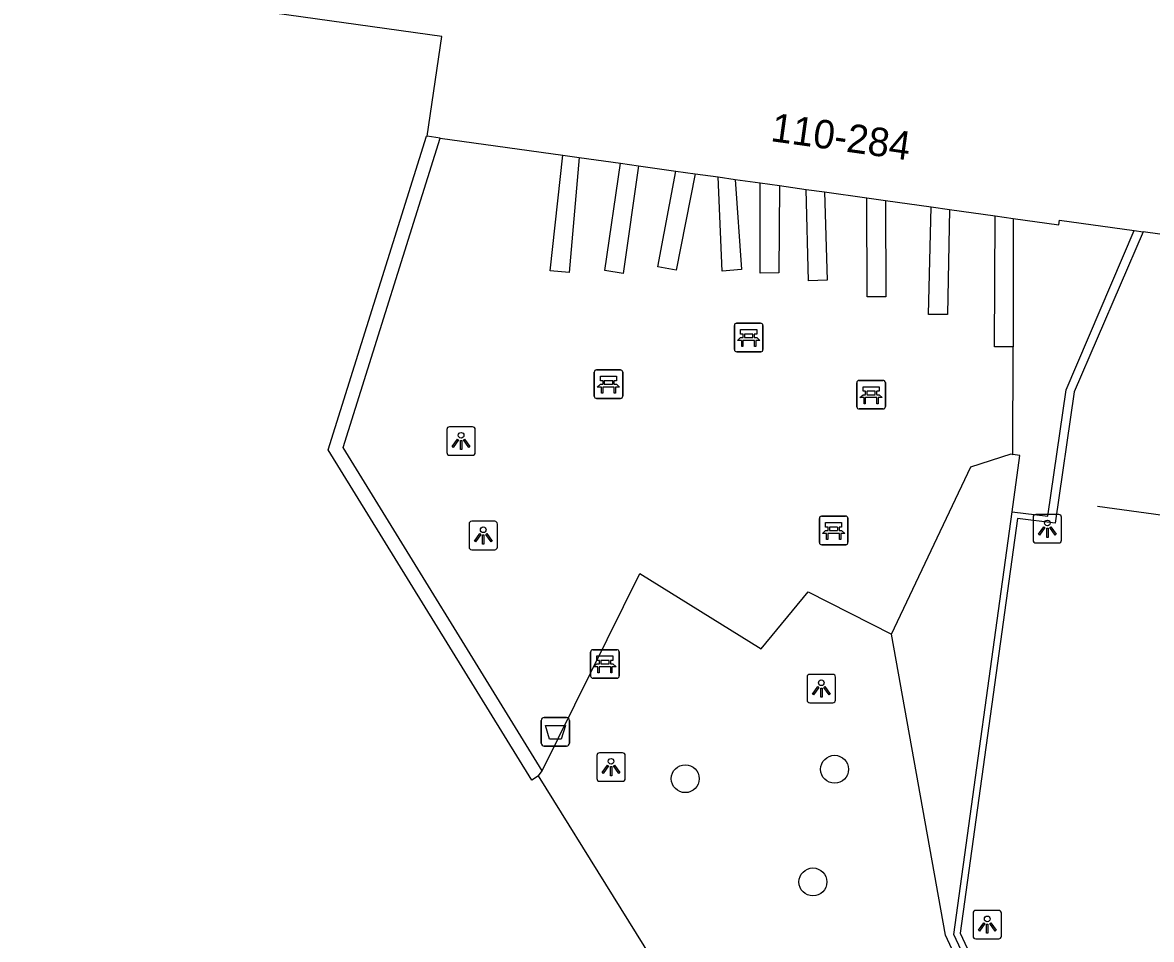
# Model space of a CAD drawing. Extents: x 155640 to 156810, y 382822 to 384046.
# Drawn here: x 156370.31 to 156409.89, y 383660.45 to 383692.57 of the extents above; entities that cross this region are included whole.
import ezdxf

# ---------------------------------------------------------------- set-up
doc = ezdxf.new("R2010")
doc.units = 0
for name, color, linetype in [('IMGEO_Afvalbak', 7, 'Continuous'), ('IMGEO_Bank', 7, 'Continuous'), ('IMGEO_Boom', 7, 'Continuous'), ('IMGEO_Lichtpunt', 7, 'Continuous'), ('IMGEO_Lijnafwatering', 7, 'Continuous'), ('IMGEO_Meer_plas_ven_vijver', 7, 'Continuous'), ('IMGEO_Muur', 7, 'Continuous'), ('IMGEO_Pand', 7, 'Continuous'), ('IMGEO_Pand_nummerreeks', 7, 'Continuous'), ('IMGEO_Voetpad_open', 7, 'Continuous')]:
    doc.layers.add(name, color=color, linetype=linetype)

msp = doc.modelspace()

# ---------------------------------------------------------------- linework, layer by layer
at = {"layer": 'IMGEO_Afvalbak'}
for p, q in [((156388.497, 383667.324), (156388.497, 383668.124)), ((156388.497, 383668.124), (156388.497, 383667.324)), ((156388.597, 383668.224), (156389.387, 383668.224)), ((156389.387, 383668.224), (156388.597, 383668.224)), ((156389.487, 383668.124), (156389.487, 383667.324)), ((156389.487, 383667.324), (156389.487, 383668.124)), ((156389.387, 383667.224), (156388.597, 383667.224)), ((156388.597, 383667.224), (156389.387, 383667.224))]:
    msp.add_line(p, q, dxfattribs=at)
msp.add_lwpolyline([(156388.64, 383667.938), (156389.344, 383667.938), (156389.195, 383667.468), (156388.789, 383667.468), (156388.64, 383667.938)], dxfattribs=at)
for centre, start, end in [((156388.597, 383668.124), 90, 180), ((156388.597, 383668.124), 90, 180), ((156389.387, 383668.124), 0, 90), ((156389.387, 383668.124), 360, 90), ((156388.597, 383667.324), 180, 270), ((156388.597, 383667.324), 180, 270), ((156389.387, 383667.324), 270, 0), ((156389.387, 383667.324), 270, 0)]:
    msp.add_arc(centre, 0.1, start, end, dxfattribs=at)
at = {"layer": 'IMGEO_Bank'}
for p, q in [((156395.27, 383681.114), (156395.27, 383681.955)), ((156395.27, 383681.955), (156395.27, 383681.114)), ((156395.345, 383682.039), (156396.186, 383682.039)), ((156396.186, 383682.039), (156395.345, 383682.039)), ((156396.27, 383681.964), (156396.27, 383681.123)), ((156396.27, 383681.123), (156396.27, 383681.964)), ((156395.967, 383681.437), (156395.574, 383681.437)), ((156395.579, 383681.545), (156395.579, 383681.651)), ((156395.623, 383681.651), (156395.623, 383681.545)), ((156395.911, 383681.657), (156395.629, 383681.657)), ((156395.629, 383681.539), (156395.911, 383681.539)), ((156395.917, 383681.545), (156395.917, 383681.651)), ((156395.961, 383681.651), (156395.961, 383681.545)), ((156396.195, 383681.039), (156395.354, 383681.039)), ((156395.354, 383681.039), (156396.195, 383681.039)), ((156390.354, 383679.479), (156390.354, 383680.32)), ((156390.354, 383680.32), (156390.354, 383679.479)), ((156390.429, 383680.404), (156391.27, 383680.404)), ((156391.27, 383680.404), (156390.429, 383680.404)), ((156391.354, 383680.329), (156391.354, 383679.488)), ((156391.354, 383679.488), (156391.354, 383680.329)), ((156391.051, 383679.802), (156390.658, 383679.802)), ((156390.663, 383679.91), (156390.663, 383680.016)), ((156390.707, 383680.016), (156390.707, 383679.91)), ((156390.995, 383680.022), (156390.713, 383680.022)), ((156390.713, 383679.904), (156390.995, 383679.904)), ((156391.001, 383679.91), (156391.001, 383680.016)), ((156391.045, 383680.016), (156391.045, 383679.91)), ((156399.562, 383679.111), (156399.562, 383679.952)), ((156399.562, 383679.952), (156399.562, 383679.111)), ((156399.637, 383680.036), (156400.478, 383680.036)), ((156400.478, 383680.036), (156399.637, 383680.036)), ((156400.562, 383679.961), (156400.562, 383679.12)), ((156400.562, 383679.12), (156400.562, 383679.961)), ((156391.279, 383679.404), (156390.438, 383679.404)), ((156390.438, 383679.404), (156391.279, 383679.404)), ((156400.259, 383679.434), (156399.866, 383679.434)), ((156399.871, 383679.542), (156399.871, 383679.648)), ((156399.915, 383679.648), (156399.915, 383679.542)), ((156400.203, 383679.654), (156399.921, 383679.654)), ((156399.921, 383679.536), (156400.203, 383679.536)), ((156400.209, 383679.542), (156400.209, 383679.648)), ((156400.253, 383679.648), (156400.253, 383679.542)), ((156400.487, 383679.036), (156399.646, 383679.036)), ((156399.646, 383679.036), (156400.487, 383679.036)), ((156398.249, 383674.354), (156398.249, 383675.195)), ((156398.249, 383675.195), (156398.249, 383674.354)), ((156398.324, 383675.279), (156399.165, 383675.279)), ((156399.165, 383675.279), (156398.324, 383675.279)), ((156399.249, 383675.204), (156399.249, 383674.363)), ((156399.249, 383674.363), (156399.249, 383675.204)), ((156398.946, 383674.677), (156398.553, 383674.677)), ((156398.558, 383674.785), (156398.558, 383674.891)), ((156398.602, 383674.891), (156398.602, 383674.785)), ((156398.89, 383674.897), (156398.608, 383674.897)), ((156398.608, 383674.779), (156398.89, 383674.779)), ((156398.896, 383674.785), (156398.896, 383674.891)), ((156398.94, 383674.891), (156398.94, 383674.785)), ((156399.174, 383674.279), (156398.333, 383674.279)), ((156398.333, 383674.279), (156399.174, 383674.279)), ((156390.228, 383669.675), (156390.228, 383670.516)), ((156390.228, 383670.516), (156390.228, 383669.675)), ((156390.303, 383670.6), (156391.144, 383670.6)), ((156391.144, 383670.6), (156390.303, 383670.6)), ((156390.537, 383670.106), (156390.537, 383670.212)), ((156390.581, 383670.212), (156390.581, 383670.106)), ((156390.869, 383670.218), (156390.587, 383670.218)), ((156390.875, 383670.106), (156390.875, 383670.212)), ((156390.919, 383670.212), (156390.919, 383670.106)), ((156391.228, 383670.525), (156391.228, 383669.684)), ((156391.228, 383669.684), (156391.228, 383670.525)), ((156390.925, 383669.998), (156390.532, 383669.998)), ((156390.587, 383670.1), (156390.869, 383670.1)), ((156391.153, 383669.6), (156390.312, 383669.6)), ((156390.312, 383669.6), (156391.153, 383669.6))]:
    msp.add_line(p, q, dxfattribs=at)
for points in [[(156395.573, 383681.657), (156395.487, 383681.657), (156395.487, 383681.818), (156396.05, 383681.818), (156396.05, 383681.657), (156395.967, 383681.657)], [(156395.517, 383681.437), (156395.375, 383681.437), (156395.487, 383681.539), (156395.573, 383681.539)], [(156395.567, 383681.43), (156395.567, 383681.223), (156395.524, 383681.223), (156395.524, 383681.43)], [(156395.967, 383681.539), (156396.05, 383681.539), (156396.162, 383681.437), (156396.023, 383681.437)], [(156396.017, 383681.43), (156396.017, 383681.223), (156395.973, 383681.223), (156395.973, 383681.43)], [(156390.657, 383680.022), (156390.571, 383680.022), (156390.571, 383680.183), (156391.134, 383680.183), (156391.134, 383680.022), (156391.051, 383680.022)], [(156390.601, 383679.802), (156390.459, 383679.802), (156390.571, 383679.904), (156390.657, 383679.904)], [(156390.651, 383679.795), (156390.651, 383679.588), (156390.608, 383679.588), (156390.608, 383679.795)], [(156391.051, 383679.904), (156391.134, 383679.904), (156391.246, 383679.802), (156391.107, 383679.802)], [(156391.101, 383679.795), (156391.101, 383679.588), (156391.057, 383679.588), (156391.057, 383679.795)], [(156399.865, 383679.654), (156399.779, 383679.654), (156399.779, 383679.815), (156400.342, 383679.815), (156400.342, 383679.654), (156400.259, 383679.654)], [(156399.809, 383679.434), (156399.667, 383679.434), (156399.779, 383679.536), (156399.865, 383679.536)], [(156399.859, 383679.427), (156399.859, 383679.22), (156399.816, 383679.22), (156399.816, 383679.427)], [(156400.259, 383679.536), (156400.342, 383679.536), (156400.454, 383679.434), (156400.315, 383679.434)], [(156400.309, 383679.427), (156400.309, 383679.22), (156400.265, 383679.22), (156400.265, 383679.427)], [(156398.552, 383674.897), (156398.466, 383674.897), (156398.466, 383675.058), (156399.029, 383675.058), (156399.029, 383674.897), (156398.946, 383674.897)], [(156398.496, 383674.677), (156398.354, 383674.677), (156398.466, 383674.779), (156398.552, 383674.779)], [(156398.546, 383674.67), (156398.546, 383674.463), (156398.503, 383674.463), (156398.503, 383674.67)], [(156398.946, 383674.779), (156399.029, 383674.779), (156399.141, 383674.677), (156399.002, 383674.677)], [(156398.996, 383674.67), (156398.996, 383674.463), (156398.952, 383674.463), (156398.952, 383674.67)], [(156390.531, 383670.218), (156390.445, 383670.218), (156390.445, 383670.379), (156391.008, 383670.379), (156391.008, 383670.218), (156390.925, 383670.218)], [(156390.475, 383669.998), (156390.333, 383669.998), (156390.445, 383670.1), (156390.531, 383670.1)], [(156390.525, 383669.991), (156390.525, 383669.784), (156390.482, 383669.784), (156390.482, 383669.991)], [(156390.925, 383670.1), (156391.008, 383670.1), (156391.12, 383669.998), (156390.981, 383669.998)], [(156390.975, 383669.991), (156390.975, 383669.784), (156390.931, 383669.784), (156390.931, 383669.991)]]:
    msp.add_lwpolyline(points, dxfattribs=at)
for centre, radius, start, end in [((156395.348, 383681.961), 0.0779, 92.4484, 184.2845), ((156395.348, 383681.961), 0.0779, 92.4484, 184.2845), ((156396.192, 383681.961), 0.0779, 2.4484, 94.2845), ((156396.192, 383681.961), 0.0779, 2.4484, 94.2845), ((156395.517, 383681.43), 0.00671, 2.8957, 87.1043), ((156395.574, 383681.43), 0.00671, 92.8957, 177.1043), ((156395.572, 383681.65), 0.00671, 2.8957, 87.1043), ((156395.572, 383681.546), 0.00671, 272.8957, 357.1043), ((156395.629, 383681.65), 0.00671, 92.8957, 177.1043), ((156395.629, 383681.546), 0.00671, 182.8957, 267.1043), ((156395.911, 383681.65), 0.00671, 2.8957, 87.1043), ((156395.911, 383681.546), 0.00671, 272.8957, 357.1043), ((156395.968, 383681.65), 0.00671, 92.8957, 177.1043), ((156395.968, 383681.546), 0.00671, 182.8957, 267.1043), ((156395.966, 383681.43), 0.00671, 2.8957, 87.1043), ((156396.023, 383681.43), 0.00671, 92.8957, 177.1043), ((156395.348, 383681.117), 0.0779, 182.4484, 274.2845), ((156395.348, 383681.117), 0.0779, 182.4484, 274.2845), ((156396.192, 383681.117), 0.0779, 272.4484, 4.2845), ((156396.192, 383681.117), 0.0779, 272.4484, 4.2845), ((156390.432, 383680.326), 0.0779, 92.4484, 184.2845), ((156390.432, 383680.326), 0.0779, 92.4484, 184.2845), ((156391.276, 383680.326), 0.0779, 2.4484, 94.2845), ((156391.276, 383680.326), 0.0779, 2.4484, 94.2845), ((156390.601, 383679.795), 0.00671, 2.8957, 87.1043), ((156390.658, 383679.795), 0.00671, 92.8957, 177.1043), ((156390.656, 383680.015), 0.00671, 2.8957, 87.1043), ((156390.656, 383679.911), 0.00671, 272.8957, 357.1043), ((156390.713, 383680.015), 0.00671, 92.8957, 177.1043), ((156390.713, 383679.911), 0.00671, 182.8957, 267.1043), ((156390.995, 383680.015), 0.00671, 2.8957, 87.1043), ((156390.995, 383679.911), 0.00671, 272.8957, 357.1043), ((156391.052, 383680.015), 0.00671, 92.8957, 177.1043), ((156391.052, 383679.911), 0.00671, 182.8957, 267.1043), ((156391.05, 383679.795), 0.00671, 2.8957, 87.1043), ((156391.107, 383679.795), 0.00671, 92.8957, 177.1043), ((156399.64, 383679.958), 0.0779, 92.4484, 184.2845), ((156399.64, 383679.958), 0.0779, 92.4484, 184.2845), ((156400.484, 383679.958), 0.0779, 2.4484, 94.2845), ((156400.484, 383679.958), 0.0779, 2.4484, 94.2845), ((156390.432, 383679.482), 0.0779, 182.4484, 274.2845), ((156390.432, 383679.482), 0.0779, 182.4484, 274.2845), ((156391.276, 383679.482), 0.0779, 272.4484, 4.2845), ((156391.276, 383679.482), 0.0779, 272.4484, 4.2845), ((156399.809, 383679.427), 0.00671, 2.8957, 87.1043), ((156399.866, 383679.427), 0.00671, 92.8957, 177.1043), ((156399.864, 383679.647), 0.00671, 2.8957, 87.1043), ((156399.864, 383679.543), 0.00671, 272.8957, 357.1043), ((156399.921, 383679.647), 0.00671, 92.8957, 177.1043), ((156399.921, 383679.543), 0.00671, 182.8957, 267.1043), ((156400.203, 383679.647), 0.00671, 2.8957, 87.1043), ((156400.203, 383679.543), 0.00671, 272.8957, 357.1043), ((156400.26, 383679.647), 0.00671, 92.8957, 177.1043), ((156400.26, 383679.543), 0.00671, 182.8957, 267.1043), ((156400.258, 383679.427), 0.00671, 2.8957, 87.1043), ((156400.315, 383679.427), 0.00671, 92.8957, 177.1043), ((156399.64, 383679.114), 0.0779, 182.4484, 274.2845), ((156399.64, 383679.114), 0.0779, 182.4484, 274.2845), ((156400.484, 383679.114), 0.0779, 272.4484, 4.2845), ((156400.484, 383679.114), 0.0779, 272.4484, 4.2845), ((156398.327, 383675.201), 0.0779, 92.4484, 184.2845), ((156398.327, 383675.201), 0.0779, 92.4484, 184.2845), ((156399.171, 383675.201), 0.0779, 2.4484, 94.2845), ((156399.171, 383675.201), 0.0779, 2.4484, 94.2845), ((156398.496, 383674.67), 0.00671, 2.8957, 87.1043), ((156398.553, 383674.67), 0.00671, 92.8957, 177.1043), ((156398.551, 383674.89), 0.00671, 2.8957, 87.1043), ((156398.551, 383674.786), 0.00671, 272.8957, 357.1043), ((156398.608, 383674.89), 0.00671, 92.8957, 177.1043), ((156398.608, 383674.786), 0.00671, 182.8957, 267.1043), ((156398.89, 383674.89), 0.00671, 2.8957, 87.1043), ((156398.89, 383674.786), 0.00671, 272.8957, 357.1043), ((156398.947, 383674.89), 0.00671, 92.8957, 177.1043), ((156398.947, 383674.786), 0.00671, 182.8957, 267.1043), ((156398.945, 383674.67), 0.00671, 2.8957, 87.1043), ((156399.002, 383674.67), 0.00671, 92.8957, 177.1043), ((156398.327, 383674.357), 0.0779, 182.4484, 274.2845), ((156398.327, 383674.357), 0.0779, 182.4484, 274.2845), ((156399.171, 383674.357), 0.0779, 272.4484, 4.2845), ((156399.171, 383674.357), 0.0779, 272.4484, 4.2845), ((156390.306, 383670.522), 0.0779, 92.4484, 184.2845), ((156390.306, 383670.522), 0.0779, 92.4484, 184.2845), ((156390.53, 383670.211), 0.00671, 2.8957, 87.1043), ((156390.587, 383670.211), 0.00671, 92.8957, 177.1043), ((156390.869, 383670.211), 0.00671, 2.8957, 87.1043), ((156390.926, 383670.211), 0.00671, 92.8957, 177.1043), ((156391.15, 383670.522), 0.0779, 2.4484, 94.2845), ((156391.15, 383670.522), 0.0779, 2.4484, 94.2845), ((156390.475, 383669.991), 0.00671, 2.8957, 87.1043), ((156390.532, 383669.991), 0.00671, 92.8957, 177.1043), ((156390.53, 383670.107), 0.00671, 272.8957, 357.1043), ((156390.587, 383670.107), 0.00671, 182.8957, 267.1043), ((156390.869, 383670.107), 0.00671, 272.8957, 357.1043), ((156390.926, 383670.107), 0.00671, 182.8957, 267.1043), ((156390.924, 383669.991), 0.00671, 2.8957, 87.1043), ((156390.981, 383669.991), 0.00671, 92.8957, 177.1043), ((156390.306, 383669.678), 0.0779, 182.4484, 274.2845), ((156390.306, 383669.678), 0.0779, 182.4484, 274.2845), ((156391.15, 383669.678), 0.0779, 272.4484, 4.2845), ((156391.15, 383669.678), 0.0779, 272.4484, 4.2845)]:
    msp.add_arc(centre, radius, start, end, dxfattribs=at)
at = {"layer": 'IMGEO_Boom'}
for centre in [(156398.781, 383666.41), (156393.545, 383666.079), (156398.021, 383662.462)]:
    msp.add_circle(centre, 0.489, dxfattribs=at)
at = {"layer": 'IMGEO_Lichtpunt'}
for p, q in [((156385.186, 383678.315), (156385.186, 383677.508)), ((156385.186, 383678.315), (156385.186, 383677.508)), ((156386.088, 383678.41), (156385.28, 383678.41)), ((156386.088, 383678.41), (156385.28, 383678.41)), ((156386.182, 383677.508), (156386.182, 383678.315)), ((156386.182, 383677.508), (156386.182, 383678.315)), ((156385.28, 383677.414), (156386.088, 383677.414)), ((156385.28, 383677.414), (156386.088, 383677.414)), ((156385.964, 383675.003), (156385.964, 383674.196)), ((156385.964, 383675.003), (156385.964, 383674.196)), ((156386.866, 383675.098), (156386.058, 383675.098)), ((156386.866, 383675.098), (156386.058, 383675.098)), ((156386.96, 383674.196), (156386.96, 383675.003)), ((156386.96, 383674.196), (156386.96, 383675.003)), ((156405.743, 383675.242), (156405.743, 383674.435)), ((156405.743, 383675.242), (156405.743, 383674.435)), ((156406.645, 383675.337), (156405.837, 383675.337)), ((156406.645, 383675.337), (156405.837, 383675.337)), ((156406.739, 383674.435), (156406.739, 383675.242)), ((156406.739, 383674.435), (156406.739, 383675.242)), ((156405.837, 383674.341), (156406.645, 383674.341)), ((156405.837, 383674.341), (156406.645, 383674.341)), ((156386.058, 383674.102), (156386.866, 383674.102)), ((156386.058, 383674.102), (156386.866, 383674.102)), ((156397.818, 383669.641), (156397.818, 383668.834)), ((156397.818, 383669.641), (156397.818, 383668.834)), ((156398.72, 383669.736), (156397.912, 383669.736)), ((156398.72, 383669.736), (156397.912, 383669.736)), ((156398.814, 383668.834), (156398.814, 383669.641)), ((156398.814, 383668.834), (156398.814, 383669.641)), ((156397.912, 383668.74), (156398.72, 383668.74)), ((156397.912, 383668.74), (156398.72, 383668.74)), ((156390.445, 383666.891), (156390.445, 383666.084)), ((156390.445, 383666.891), (156390.445, 383666.084)), ((156391.347, 383666.986), (156390.539, 383666.986)), ((156391.347, 383666.986), (156390.539, 383666.986)), ((156391.441, 383666.084), (156391.441, 383666.891)), ((156391.441, 383666.084), (156391.441, 383666.891)), ((156390.539, 383665.99), (156391.347, 383665.99)), ((156390.539, 383665.99), (156391.347, 383665.99)), ((156403.636, 383661.368), (156403.636, 383660.561)), ((156403.636, 383661.368), (156403.636, 383660.561)), ((156404.538, 383661.463), (156403.73, 383661.463)), ((156404.538, 383661.463), (156403.73, 383661.463)), ((156404.632, 383660.561), (156404.632, 383661.368)), ((156404.632, 383660.561), (156404.632, 383661.368)), ((156403.73, 383660.467), (156404.538, 383660.467)), ((156403.73, 383660.467), (156404.538, 383660.467))]:
    msp.add_line(p, q, dxfattribs=at)
for points in [[(156385.56, 383677.979), (156385.599, 383677.951), (156385.411, 383677.689), (156385.373, 383677.716), (156385.56, 383677.979)], [(156385.662, 383677.931), (156385.709, 383677.931), (156385.709, 383677.609), (156385.662, 383677.609), (156385.662, 383677.931)], [(156385.772, 383677.951), (156385.81, 383677.978), (156385.997, 383677.716), (156385.958, 383677.688), (156385.772, 383677.951)], [(156386.338, 383674.667), (156386.377, 383674.639), (156386.189, 383674.377), (156386.151, 383674.404), (156386.338, 383674.667)], [(156386.44, 383674.619), (156386.487, 383674.619), (156386.487, 383674.297), (156386.44, 383674.297), (156386.44, 383674.619)], [(156386.55, 383674.639), (156386.588, 383674.666), (156386.775, 383674.404), (156386.736, 383674.376), (156386.55, 383674.639)], [(156406.117, 383674.906), (156406.156, 383674.878), (156405.968, 383674.616), (156405.93, 383674.643), (156406.117, 383674.906)], [(156406.219, 383674.858), (156406.266, 383674.858), (156406.266, 383674.536), (156406.219, 383674.536), (156406.219, 383674.858)], [(156406.329, 383674.878), (156406.367, 383674.905), (156406.554, 383674.643), (156406.515, 383674.615), (156406.329, 383674.878)], [(156398.192, 383669.305), (156398.231, 383669.277), (156398.043, 383669.015), (156398.005, 383669.042), (156398.192, 383669.305)], [(156398.294, 383669.257), (156398.341, 383669.257), (156398.341, 383668.935), (156398.294, 383668.935), (156398.294, 383669.257)], [(156398.404, 383669.277), (156398.442, 383669.304), (156398.629, 383669.042), (156398.59, 383669.014), (156398.404, 383669.277)], [(156390.819, 383666.555), (156390.858, 383666.527), (156390.67, 383666.265), (156390.632, 383666.292), (156390.819, 383666.555)], [(156390.921, 383666.507), (156390.968, 383666.507), (156390.968, 383666.185), (156390.921, 383666.185), (156390.921, 383666.507)], [(156391.031, 383666.527), (156391.069, 383666.554), (156391.256, 383666.292), (156391.217, 383666.264), (156391.031, 383666.527)], [(156404.01, 383661.032), (156404.049, 383661.004), (156403.861, 383660.742), (156403.823, 383660.769), (156404.01, 383661.032)], [(156404.112, 383660.984), (156404.159, 383660.984), (156404.159, 383660.662), (156404.112, 383660.662), (156404.112, 383660.984)], [(156404.222, 383661.004), (156404.26, 383661.031), (156404.447, 383660.769), (156404.408, 383660.741), (156404.222, 383661.004)]]:
    msp.add_lwpolyline(points, dxfattribs=at)
for centre in [(156385.685, 383678.113), (156406.242, 383675.04), (156386.463, 383674.801), (156398.317, 383669.439), (156390.944, 383666.689), (156404.135, 383661.166)]:
    msp.add_circle(centre, 0.0994, dxfattribs=at)
for centre, start, end in [((156385.28, 383678.315), 90, 180), ((156385.28, 383678.315), 90, 180), ((156386.088, 383678.315), 0, 90), ((156386.088, 383678.315), 0, 90), ((156385.28, 383677.508), 180, 270), ((156385.28, 383677.508), 180, 270), ((156386.088, 383677.508), 270, 0), ((156386.088, 383677.508), 270, 360), ((156386.058, 383675.003), 90, 180), ((156386.058, 383675.003), 90, 180), ((156386.866, 383675.003), 0, 90), ((156386.866, 383675.003), 0, 90), ((156405.837, 383675.242), 90, 180), ((156405.837, 383675.242), 90, 180), ((156406.645, 383675.242), 0, 90), ((156406.645, 383675.242), 0, 90), ((156386.058, 383674.196), 180, 270), ((156386.058, 383674.196), 180, 270), ((156386.866, 383674.196), 270, 0), ((156386.866, 383674.196), 270, 360), ((156405.837, 383674.435), 180, 270), ((156405.837, 383674.435), 180, 270), ((156406.645, 383674.435), 270, 0), ((156406.645, 383674.435), 270, 360), ((156397.912, 383669.641), 90, 180), ((156397.912, 383669.641), 90, 180), ((156398.72, 383669.641), 0, 90), ((156398.72, 383669.641), 0, 90), ((156397.912, 383668.834), 180, 270), ((156397.912, 383668.834), 180, 270), ((156398.72, 383668.834), 270, 0), ((156398.72, 383668.834), 270, 360), ((156390.539, 383666.891), 90, 180), ((156390.539, 383666.891), 90, 180), ((156391.347, 383666.891), 0, 90), ((156391.347, 383666.891), 0, 90), ((156390.539, 383666.084), 180, 270), ((156390.539, 383666.084), 180, 270), ((156391.347, 383666.084), 270, 0), ((156391.347, 383666.084), 270, 360), ((156403.73, 383661.368), 90, 180), ((156403.73, 383661.368), 90, 180), ((156404.538, 383661.368), 0, 90), ((156404.538, 383661.368), 0, 90), ((156403.73, 383660.561), 180, 270), ((156403.73, 383660.561), 180, 270), ((156404.538, 383660.561), 270, 0), ((156404.538, 383660.561), 270, 360)]:
    msp.add_arc(centre, 0.0946, start, end, dxfattribs=at)
at = {"layer": 'IMGEO_Lijnafwatering'}
msp.add_lwpolyline([(156425.823, 383673.176), (156408.001, 383675.614)], dxfattribs=at)
at = {"layer": 'IMGEO_Meer_plas_ven_vijver'}
msp.add_lwpolyline([(156398.921, 383649.266), (156388.405, 383666.182)], dxfattribs=at)
at = {"layer": 'IMGEO_Muur'}
for points in [[(156388.405, 383666.182), (156388.164, 383666.029), (156381.02, 383677.599), (156384.468, 383688.597), (156384.494, 383688.593)], [(156388.526, 383666.353), (156381.554, 383677.681), (156384.951, 383688.529)], [(156405.007, 383675.431), (156406.259, 383675.274), (156406.898, 383679.708), (156409.281, 383685.287)], [(156409.602, 383685.242), (156407.185, 383679.634), (156406.522, 383675.039), (156405.194, 383675.202), (156403.183, 383660.665), (156406.798, 383652.916)], [(156406.607, 383652.828), (156402.962, 383660.62), (156405.007, 383675.431)], [(156388.405, 383666.182), (156388.526, 383666.353)]]:
    msp.add_lwpolyline(points, dxfattribs=at)
at = {"layer": 'IMGEO_Pand'}
for points in [[(156384.494, 383688.593), (156385.008, 383692.092), (156370.759, 383694.081), (156370.875, 383694.938), (156371.987, 383694.787), (156372.993, 383701.906), (156370.31, 383702.303), (156370.445, 383703.217), (156371.61, 383703.045), (156372.608, 383710.192), (156371.421, 383710.367), (156371.545, 383711.205), (156417.388, 383704.778)], [(156417.705, 383704.734), (156425.581, 383703.63), (156423.21, 383686.732), (156415.328, 383687.843), (156414.878, 383684.502), (156409.602, 383685.242)], [(156384.951, 383688.529), (156384.494, 383688.593)], [(156384.951, 383688.529), (156389.258, 383687.926)], [(156389.258, 383687.926), (156389.824, 383687.847)], [(156389.824, 383687.847), (156391.276, 383687.644)], [(156391.276, 383687.644), (156391.904, 383687.556)], [(156391.904, 383687.556), (156393.217, 383687.372)], [(156393.217, 383687.372), (156393.895, 383687.277)], [(156393.895, 383687.277), (156394.698, 383687.164)], [(156394.698, 383687.164), (156395.301, 383687.08)], [(156395.301, 383687.08), (156396.168, 383686.959)], [(156396.168, 383686.959), (156396.849, 383686.863)], [(156396.849, 383686.863), (156397.791, 383686.731)], [(156397.791, 383686.731), (156398.426, 383686.642)], [(156398.426, 383686.642), (156399.917, 383686.433)], [(156399.917, 383686.433), (156400.565, 383686.342)], [(156400.565, 383686.342), (156402.164, 383686.118)], [(156402.164, 383686.118), (156402.809, 383686.028)], [(156402.809, 383686.028), (156404.416, 383685.803)], [(156404.416, 383685.803), (156405.047, 383685.715)], [(156405.047, 383685.715), (156406.644, 383685.491), (156406.666, 383685.653), (156409.281, 383685.287)], [(156409.281, 383685.287), (156409.602, 383685.242)]]:
    msp.add_lwpolyline(points, dxfattribs=at)
at = {"layer": 'IMGEO_Voetpad_open'}
for points in [[(156389.824, 383687.847), (156389.47, 383683.817), (156388.804, 383683.878), (156389.258, 383687.926)], [(156391.904, 383687.556), (156391.371, 383683.78), (156390.721, 383683.892), (156391.276, 383687.644)], [(156393.895, 383687.277), (156393.224, 383683.901), (156392.588, 383684.021), (156393.217, 383687.372)], [(156395.301, 383687.08), (156395.513, 383683.918), (156394.84, 383683.869), (156394.698, 383687.164)], [(156396.849, 383686.863), (156396.83, 383683.801), (156396.17, 383683.795), (156396.168, 383686.959)], [(156398.426, 383686.642), (156398.527, 383683.552), (156397.867, 383683.524), (156397.791, 383686.731)], [(156400.565, 383686.342), (156400.582, 383682.965), (156399.929, 383682.964), (156399.917, 383686.433)], [(156402.809, 383686.028), (156402.74, 383682.34), (156402.071, 383682.34), (156402.164, 383686.118)], [(156405.04, 383681.216), (156404.394, 383681.208), (156404.416, 383685.803)], [(156405.047, 383685.715), (156405.04, 383681.216)], [(156405.034, 383677.437), (156405.04, 383681.216)], [(156400.777, 383671.143), (156403.554, 383677.003), (156404.977, 383677.465), (156405.034, 383677.437)], [(156405.007, 383675.431), (156405.277, 383677.405), (156405.034, 383677.437)], [(156388.526, 383666.353), (156391.957, 383673.269), (156396.207, 383670.632), (156397.859, 383672.624), (156400.777, 383671.143)], [(156406.329, 383652.699), (156402.667, 383660.593), (156400.777, 383671.143)]]:
    msp.add_lwpolyline(points, dxfattribs=at)

# ---------------------------------------------------------------- texts
at = {"layer": 'IMGEO_Pand_nummerreeks'}
msp.add_text('110-284', height=1, rotation=352.0302, dxfattribs=at).set_placement((156396.511, 383688.425))

doc.saveas('drawing.dxf')
